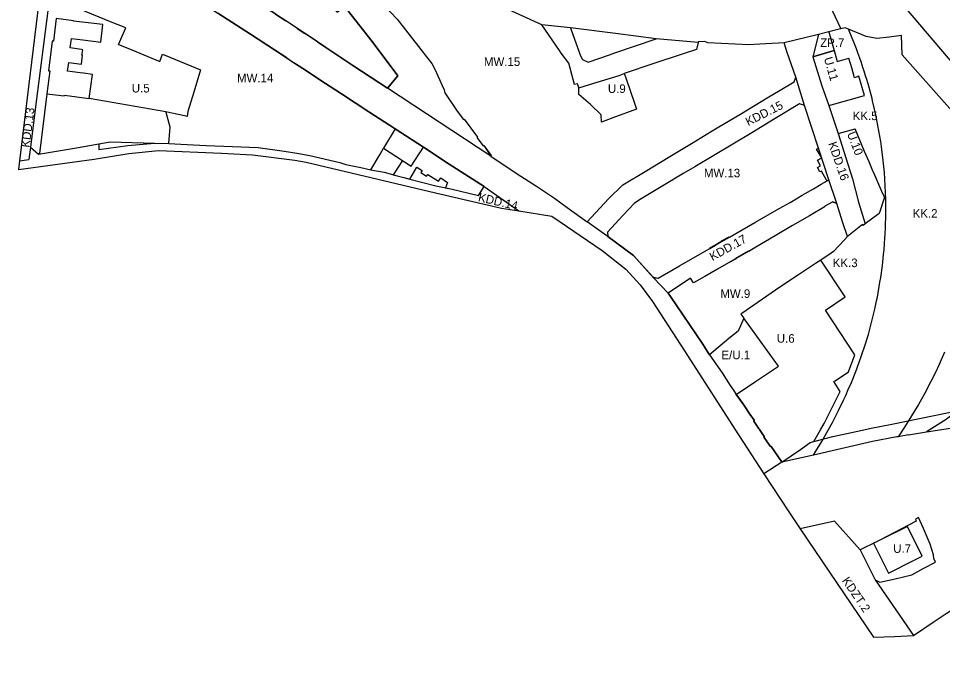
# Model space of a CAD drawing. Extents: x 7424719 to 7426158, y 5545504 to 5546892.
# Drawn here: x 7425136 to 7425675, y 5545534 to 5545910 of the extents above; entities that cross this region are included whole.
import ezdxf

# ---------------------------------------------------------------- set-up
doc = ezdxf.new("R2010")
doc.units = 0
for name, color, linetype in [('Linia Zabudowy Nieprzekraczalna', 7, 'Continuous'), ('Linia Zabudowy Obowiązujaca', 7, 'Continuous'), ('Linie Rozgraniczajace', 7, 'Continuous'), ('Oznaczenia Przeznaczenia', 7, 'Continuous')]:
    doc.layers.add(name, color=color, linetype=linetype)

msp = doc.modelspace()

# ---------------------------------------------------------------- linework, layer by layer
at = {"layer": 'Linia Zabudowy Nieprzekraczalna'}
for p, q in [((7425221.95, 5545855.04), (7425177.27, 5545862.88)), ((7425619.91, 5545782.28), (7425617.12, 5545790.15)), ((7425536.53, 5545758.98), (7425529.93, 5545755.27))]:
    msp.add_line(p, q, dxfattribs=at)
for points in [[(7425342.48, 5545896.07), (7425330.08, 5545911.69), (7425326.2, 5545916.65), (7425322, 5545913.22), (7425306.22, 5545929.93), (7425307.99, 5545931.44), (7425306.98, 5545931.69), (7425284.21, 5545937.96), (7425280.74, 5545938.92)], [(7425462.94, 5545868.99), (7425462.27, 5545871.4), (7425460.44, 5545870.89), (7425458.92, 5545876.89), (7425457.98, 5545880.44), (7425457.18, 5545883.45), (7425452.71, 5545889.29), (7425451.73, 5545890.74), (7425441.52, 5545905.84)], [(7425538.37, 5545895.3), (7425536.66, 5545895.99), (7425532.74, 5545895.93), (7425532.61, 5545895.42), (7425531.65, 5545891.5)], [(7425374.15, 5545887.09), (7425377.13, 5545883.26), (7425379.08, 5545879.51), (7425383.23, 5545870.4), (7425384.4, 5545867.84), (7425384.71, 5545866.06), (7425392.04, 5545855.48)], [(7425152.54, 5545865.55), (7425148.22, 5545830.64), (7425147.61, 5545830.39), (7425168.55, 5545833.86), (7425182.86, 5545836.3), (7425189.52, 5545837.43), (7425215.38, 5545836.72), (7425223.7, 5545836.49)], [(7425608.96, 5545858.71), (7425614.36, 5545842.32), (7425618.86, 5545828.14)], [(7425341.6, 5545821.17), (7425347.02, 5545830.29), (7425349.08, 5545833.88)], [(7425360.13, 5545826.6), (7425354.69, 5545818.22), (7425356.89, 5545817.58), (7425360.84, 5545816.68)], [(7425622.81, 5545815.98), (7425626.27, 5545802.36), (7425630.2, 5545789.7)], [(7425511.14, 5545811.23), (7425499.48, 5545804.26), (7425495.46, 5545801.77)], [(7425539.25, 5545713.16), (7425546.66, 5545702.61), (7425551.43, 5545695.31), (7425553.25, 5545692.5), (7425554.93, 5545690)], [(7425592.45, 5545657.95), (7425598.08, 5545661.94), (7425600.26, 5545662.54), (7425611.3, 5545665.5), (7425627.63, 5545668.96), (7425628.68, 5545669.19), (7425632.77, 5545670.07), (7425645.71, 5545672.72), (7425810.15, 5545706.28)]]:
    msp.add_lwpolyline(points, dxfattribs=at)
for points in [[(7425481.01, 5545888.36), (7425483.99, 5545889.38), (7425508.14, 5545897.68), (7425484.45, 5545900.73), (7425458.11, 5545904.1), (7425458.54, 5545902.88), (7425463.92, 5545887.7), (7425465.26, 5545885.66), (7425468.42, 5545884.03)], [(7425643.87, 5545585.67), (7425658.76, 5545593.24), (7425663.48, 5545595.64), (7425654.83, 5545612.88), (7425639.21, 5545605.19), (7425637.08, 5545604.14), (7425635.08, 5545603.18)]]:
    msp.add_lwpolyline(points, close=True, dxfattribs=at)
at = {"layer": 'Linia Zabudowy Obowiązujaca'}
msp.add_line((7425618.86, 5545828.14), (7425622.81, 5545815.98), dxfattribs=at)
for points in [[(7425280.74, 5545938.92), (7425271.38, 5545940.8), (7425262.7, 5545927.12), (7425267.77, 5545923.82), (7425267.93, 5545924.09), (7425272.74, 5545920.96), (7425272.54, 5545920.73), (7425280.99, 5545915.23), (7425281.18, 5545915.48), (7425286.07, 5545912.28), (7425285.91, 5545912.04), (7425291.9, 5545908.14), (7425292.06, 5545908.38), (7425298.88, 5545903.93), (7425298.67, 5545903.67), (7425303.12, 5545900.73), (7425303.34, 5545900.95), (7425310.54, 5545895.99), (7425310.47, 5545895.88), (7425315.42, 5545892.62), (7425331.12, 5545882.16), (7425351.27, 5545868.89), (7425357.35, 5545876.12), (7425342.48, 5545896.07)], [(7425441.52, 5545905.84), (7425406, 5545922.06), (7425398.41, 5545925.48), (7425384.75, 5545932.02), (7425380.53, 5545933.18), (7425380.79, 5545934.47), (7425361.98, 5545938.37), (7425355.08, 5545935.83), (7425344.31, 5545931.84), (7425340.9, 5545926.19)], [(7425340.9, 5545926.19), (7425357.03, 5545909.09), (7425370.81, 5545891.45), (7425374.15, 5545887.09)], [(7425360.84, 5545816.68), (7425364.36, 5545815.65), (7425368.49, 5545822.7), (7425371.48, 5545820.75), (7425370.72, 5545819.64), (7425374.18, 5545817.39), (7425374.9, 5545818.53), (7425381.16, 5545814.6), (7425382.41, 5545816.57), (7425385.82, 5545814.25), (7425386.36, 5545813.74), (7425385.19, 5545810.66), (7425388.32, 5545809.98), (7425404.43, 5545806.22), (7425407.69, 5545811.38), (7425387.39, 5545824.41), (7425372.32, 5545834.37), (7425355.76, 5545845.1), (7425340.37, 5545855.11), (7425324.58, 5545865.5), (7425311.75, 5545873.76), (7425304.02, 5545878.88), (7425299.79, 5545881.68), (7425296.67, 5545883.6), (7425296.6, 5545883.46), (7425292.48, 5545886.29), (7425292.6, 5545886.47), (7425285.44, 5545891.24), (7425271.34, 5545900.36), (7425252.35, 5545912.68)], [(7425392.04, 5545855.48), (7425395.72, 5545850.48), (7425396.14, 5545850.76), (7425403.95, 5545840.28), (7425403.55, 5545839.98), (7425407.27, 5545835.08), (7425407.66, 5545835.36), (7425411.91, 5545829.53), (7425411.67, 5545829.21), (7425427.04, 5545818.91), (7425438.24, 5545811.68), (7425448.82, 5545804.62), (7425456.25, 5545799.25), (7425467.98, 5545790.86), (7425480.31, 5545804.19), (7425488.77, 5545812.5), (7425501.66, 5545820.28), (7425516.17, 5545828.96), (7425529.68, 5545837.09), (7425539.86, 5545843.25), (7425543.71, 5545845.6), (7425558.03, 5545854.05), (7425573.05, 5545863.18), (7425580.63, 5545867.69), (7425588.71, 5545872.49), (7425589.64, 5545875.21), (7425584.72, 5545889.72), (7425582.81, 5545895.28), (7425568.74, 5545894.54), (7425562.22, 5545894.09), (7425538.37, 5545895.3)], [(7425531.65, 5545891.5), (7425522.67, 5545888.42), (7425506.88, 5545883.22), (7425489.51, 5545877.32)], [(7425612.14, 5545890.74), (7425599.6, 5545887.04), (7425604.91, 5545870.29), (7425608.96, 5545858.71)], [(7425495.46, 5545801.77), (7425488.97, 5545794.78), (7425479.68, 5545784.76), (7425479.93, 5545782.16), (7425494.97, 5545771.18), (7425506.2, 5545758.74), (7425506.35, 5545758.83), (7425506.66, 5545758.47), (7425509.31, 5545757.86), (7425521.77, 5545765.13), (7425528.25, 5545768.84), (7425539.46, 5545775.24), (7425539.34, 5545775.44), (7425539.88, 5545775.75), (7425542.1, 5545777.02), (7425542.46, 5545777.27), (7425545.97, 5545779.36), (7425546.38, 5545779.62), (7425550.73, 5545782.14), (7425550.84, 5545781.95), (7425550.95, 5545781.76), (7425565.77, 5545790.32), (7425579.89, 5545798.52), (7425586.31, 5545802.11), (7425590.85, 5545804.78), (7425593.43, 5545806.35), (7425599.92, 5545810.04), (7425604.45, 5545812.72), (7425607.93, 5545814.73), (7425607.49, 5545815.49), (7425604.61, 5545820.45), (7425603.74, 5545819.92), (7425602.31, 5545822.52), (7425604.17, 5545823.58), (7425602.38, 5545826.74), (7425604.79, 5545828.08), (7425601.83, 5545833.24), (7425602.95, 5545833.77), (7425594.8, 5545858.62), (7425591.92, 5545859.71), (7425577.67, 5545851.09), (7425563.96, 5545842.82), (7425530.71, 5545822.94), (7425524.41, 5545819.19), (7425511.14, 5545811.23)], [(7425223.7, 5545836.49), (7425230.61, 5545836.11), (7425245.49, 5545835.43), (7425260.79, 5545834.74), (7425275.88, 5545834.26), (7425291, 5545832.06), (7425298.36, 5545830.97), (7425305.98, 5545829.48), (7425323.44, 5545825.4), (7425327.04, 5545824.2), (7425335.7, 5545822.57), (7425341.6, 5545821.17)], [(7425349.08, 5545833.88), (7425360.13, 5545826.6)], [(7425617.12, 5545790.15), (7425613.63, 5545801.56), (7425611.22, 5545802.47), (7425606.64, 5545799.92), (7425606.73, 5545799.78), (7425597.65, 5545794.33), (7425587.78, 5545788.58), (7425577.55, 5545782.59), (7425566.29, 5545776.02), (7425562.19, 5545773.45), (7425562.1, 5545773.61), (7425554.75, 5545769.39), (7425554.77, 5545769.2), (7425550.37, 5545766.87), (7425544.05, 5545763.21), (7425536.53, 5545758.98)], [(7425529.93, 5545755.27), (7425528.14, 5545757.98), (7425515.23, 5545749.15), (7425516.56, 5545747.2), (7425534.99, 5545720.07), (7425539.25, 5545713.16)], [(7425555.2, 5545689.62), (7425559.1, 5545684.08), (7425562.89, 5545678.6), (7425565.41, 5545675.01), (7425565.18, 5545674.43), (7425571.21, 5545665.45), (7425571.22, 5545665), (7425574.75, 5545659.81), (7425575.35, 5545659.7), (7425581.25, 5545650.86), (7425581.5, 5545650.49), (7425592.45, 5545657.95)]]:
    msp.add_lwpolyline(points, dxfattribs=at)
msp.add_lwpolyline([(7425179.04, 5545876.88), (7425173.9, 5545877.53), (7425171.95, 5545877.77), (7425164.58, 5545878.73), (7425165.25, 5545883.79), (7425172.64, 5545882.83), (7425172.91, 5545884.65), (7425173.28, 5545888.02), (7425172.99, 5545888.05), (7425173.4, 5545891.27), (7425172.75, 5545891.35), (7425166.12, 5545892.29), (7425166.81, 5545897.8), (7425173.45, 5545896.96), (7425183.92, 5545895.77), (7425185.08, 5545906.02), (7425168.07, 5545907.92), (7425168.1, 5545908.19), (7425157.99, 5545909.45), (7425156.34, 5545896.18), (7425155.61, 5545896.27), (7425153.46, 5545878.96), (7425154.19, 5545878.87), (7425152.54, 5545865.55), (7425162.68, 5545864.27), (7425162.77, 5545864.68), (7425177.27, 5545862.88)], close=True, dxfattribs=at)
at = {"layer": 'Linie Rozgraniczajace'}
for p, q in [((7425978.47, 5545533.55), (7425205.67, 5546443.4)), ((7425609.01, 5545901.71), (7425612.14, 5545890.74)), ((7425411.67, 5545829.21), (7425351.27, 5545868.89)), ((7425222.08, 5545854.57), (7425221.95, 5545855.04)), ((7425224.45, 5545846), (7425222.08, 5545854.57)), ((7425223.7, 5545836.49), (7425224.45, 5545846)), ((7425614.36, 5545842.32), (7425624.4, 5545845.18)), ((7425611.22, 5545802.47), (7425613.63, 5545801.56)), ((7425515.23, 5545749.15), (7425506.63, 5545758.14)), ((7425581.5, 5545650.49), (7425571.06, 5545643.7)), ((7425664.15, 5545611.8), (7425661.37, 5545618.17)), ((7425657.45, 5545584.76), (7425664.36, 5545588.57)), ((7425647.58, 5545582.47), (7425657.45, 5545584.76)), ((7425636.06, 5545581.74), (7425658.39, 5545549.4))]:
    msp.add_line(p, q, dxfattribs=at)
for points in [[(7425151.54, 5545949.85), (7425136.55, 5545826.39), (7425135.93, 5545821.28), (7425180.05, 5545827.35), (7425200.35, 5545830.6), (7425217.76, 5545832.37), (7425254.45, 5545830.9), (7425272.5, 5545829.97), (7425297.34, 5545826.88), (7425303.93, 5545825.65), (7425379.35, 5545807.74), (7425417.93, 5545798.79), (7425427.91, 5545797.21), (7425447.26, 5545794.15), (7425476.64, 5545774.16), (7425490.4, 5545763.21), (7425498.87, 5545754.09), (7425505.93, 5545744.24), (7425524.66, 5545715.41), (7425554.05, 5545669.83), (7425571.06, 5545643.7), (7425585.53, 5545621.47), (7425592.25, 5545611.54), (7425635.03, 5545548.39)], [(7425151.54, 5545949.85), (7425151.94, 5545949.88), (7425160.68, 5545949.78), (7425156.01, 5545937.51), (7425154.82, 5545928.06), (7425153.94, 5545921.7), (7425153.22, 5545915.57), (7425146.14, 5545859.53), (7425142.98, 5545834.37), (7425142.02, 5545827.23)], [(7425213.97, 5545937.88), (7425235.03, 5545924), (7425252.35, 5545912.68), (7425271.34, 5545900.36), (7425285.44, 5545891.24), (7425299.79, 5545881.68), (7425304.02, 5545878.88), (7425311.75, 5545873.76), (7425324.58, 5545865.5), (7425340.37, 5545855.11), (7425355.76, 5545845.1), (7425372.32, 5545834.37), (7425387.39, 5545824.41), (7425407.69, 5545811.38)], [(7425307.99, 5545931.44), (7425306.22, 5545929.93), (7425322, 5545913.22), (7425326.2, 5545916.65), (7425330.08, 5545911.69), (7425342.48, 5545896.07), (7425357.35, 5545876.12), (7425351.27, 5545868.89), (7425331.12, 5545882.16), (7425315.42, 5545892.62), (7425310.47, 5545895.88), (7425291.9, 5545908.14), (7425262.7, 5545927.12)], [(7425340.9, 5545926.19), (7425357.03, 5545909.09), (7425370.81, 5545891.45), (7425374.15, 5545887.09), (7425377.13, 5545883.26), (7425379.08, 5545879.51), (7425383.23, 5545870.4), (7425384.4, 5545867.84), (7425384.71, 5545866.06), (7425392.04, 5545855.48), (7425395.72, 5545850.48), (7425396.14, 5545850.76), (7425403.95, 5545840.28), (7425403.55, 5545839.98), (7425407.27, 5545835.08), (7425407.66, 5545835.36), (7425411.67, 5545829.21)], [(7425194.35, 5545894.32), (7425198.5, 5545903.98), (7425189.71, 5545907.56), (7425172.04, 5545914.73), (7425169.28, 5545915.89), (7425164.22, 5545917.84), (7425153.94, 5545921.7)], [(7425609.38, 5545917.44), (7425616.05, 5545903.52), (7425615.83, 5545903.48), (7425609.01, 5545901.71), (7425602.96, 5545900.23), (7425582.81, 5545895.28), (7425568.74, 5545894.54), (7425562.22, 5545894.09), (7425538.37, 5545895.3), (7425536.66, 5545895.99), (7425532.74, 5545895.93), (7425532.61, 5545895.42), (7425508.14, 5545897.68), (7425484.45, 5545900.73), (7425458.11, 5545904.1), (7425441.52, 5545905.84), (7425406, 5545922.06)], [(7425599.93, 5545654.67), (7425601.39, 5545656.86), (7425604.86, 5545662.54), (7425607.88, 5545667.92), (7425611.15, 5545673.75), (7425613.48, 5545678.31), (7425614.69, 5545680.65), (7425617.59, 5545686.69), (7425618.92, 5545689.45), (7425620.33, 5545692.84), (7425622.19, 5545697.01), (7425624.71, 5545703.35), (7425626.54, 5545708.28), (7425628.25, 5545713.29), (7425629.8, 5545717.82), (7425632.02, 5545725.01), (7425633.85, 5545731.95), (7425635.8, 5545739.89), (7425636.84, 5545744.65), (7425637.33, 5545746.89), (7425638.79, 5545755.49), (7425639.26, 5545758.24), (7425640.21, 5545765.26), (7425640.9, 5545771.82), (7425641.19, 5545774.53), (7425641.7, 5545781.4), (7425641.84, 5545783.17), (7425642.05, 5545787.82), (7425642.21, 5545794.88), (7425642.25, 5545796.71), (7425642.24, 5545802.65), (7425642.2, 5545803.62), (7425642.05, 5545808.01), (7425641.92, 5545811.83), (7425641.65, 5545815.75), (7425641.37, 5545819.68), (7425640.69, 5545826.55), (7425639.92, 5545833.12), (7425639.26, 5545837.65), (7425638.17, 5545843.96), (7425636.39, 5545853.36), (7425635.67, 5545856.49), (7425634.53, 5545861.43), (7425634.19, 5545862.88), (7425633.03, 5545867.14), (7425632.24, 5545870.04), (7425631.07, 5545873.86), (7425630.42, 5545875.99), (7425629.55, 5545878.84), (7425629.07, 5545880.41), (7425627.77, 5545884.11), (7425627, 5545886.26), (7425625.87, 5545889.46), (7425625.01, 5545891.89), (7425623.85, 5545894.81), (7425622.57, 5545898.03), (7425620.49, 5545903.25)], [(7425620.49, 5545903.25), (7425618.56, 5545904.08), (7425616.05, 5545903.52)], [(7425636.98, 5545897.89), (7425630.66, 5545898.9), (7425620.49, 5545903.25)], [(7425602.96, 5545900.23), (7425599.6, 5545887.04)], [(7425651.34, 5545899.61), (7425644.25, 5545898.69), (7425636.98, 5545897.89)], [(7425696.1, 5545838.33), (7425651.74, 5545888.31), (7425651.34, 5545899.61)], [(7425194.35, 5545894.32), (7425199.69, 5545892.12), (7425218.4, 5545884.37), (7425220.09, 5545888.6), (7425224.2, 5545886.97), (7425242.18, 5545879.57), (7425238.37, 5545866.52), (7425234.87, 5545855.19), (7425234.37, 5545852.37), (7425233.8, 5545852.49), (7425225.51, 5545854.28), (7425221.95, 5545855.04)], [(7425599.6, 5545887.04), (7425604.91, 5545870.29), (7425608.96, 5545858.71), (7425614.36, 5545842.32), (7425618.86, 5545828.14), (7425622.81, 5545815.98), (7425626.27, 5545802.36), (7425630.2, 5545789.7), (7425628.93, 5545788.67), (7425628.52, 5545789.2), (7425619.91, 5545782.28), (7425617.12, 5545790.15), (7425613.63, 5545801.56), (7425608.93, 5545815.31), (7425602.95, 5545833.77), (7425594.8, 5545858.62), (7425589.64, 5545875.21), (7425584.72, 5545889.72), (7425582.81, 5545895.28)], [(7425599.6, 5545887.04), (7425612.14, 5545890.74), (7425613.82, 5545884.39), (7425620.6, 5545886.28)], [(7425608.96, 5545858.71), (7425620.74, 5545862.02), (7425629.74, 5545864.6), (7425626.52, 5545875.76), (7425623.99, 5545874.96), (7425622.3, 5545880.63), (7425620.6, 5545886.28)], [(7425489.51, 5545877.32), (7425490.19, 5545875.38), (7425493.32, 5545866.39), (7425495.13, 5545861.17), (7425496.7, 5545856.65), (7425482.84, 5545851.55), (7425476.25, 5545849.03), (7425476.13, 5545853.34), (7425469.78, 5545859.35), (7425462.94, 5545865.21), (7425462.94, 5545868.99), (7425469.17, 5545870.91), (7425486.61, 5545876.27), (7425489.51, 5545877.32)], [(7425594.8, 5545858.62), (7425591.92, 5545859.71), (7425577.67, 5545851.09), (7425563.96, 5545842.82), (7425530.71, 5545822.94), (7425524.41, 5545819.19), (7425511.14, 5545811.23), (7425499.48, 5545804.26), (7425495.46, 5545801.77), (7425488.97, 5545794.78), (7425479.68, 5545784.76), (7425479.93, 5545782.16), (7425476.09, 5545784.93), (7425467.98, 5545790.86), (7425480.31, 5545804.19), (7425488.77, 5545812.5), (7425501.66, 5545820.28), (7425516.17, 5545828.96), (7425529.68, 5545837.09), (7425539.86, 5545843.25), (7425543.71, 5545845.6), (7425558.03, 5545854.05), (7425573.05, 5545863.18), (7425580.63, 5545867.69), (7425588.71, 5545872.49), (7425589.64, 5545875.21)], [(7425355.76, 5545845.1), (7425349.08, 5545833.88), (7425365.16, 5545823.34), (7425372.32, 5545834.37)], [(7425642.2, 5545803.62), (7425641.39, 5545805.29), (7425639.98, 5545808.43), (7425635.79, 5545818.13), (7425634.5, 5545821.01), (7425632.47, 5545825.86), (7425629.74, 5545831.78), (7425624.4, 5545845.18)], [(7425142.98, 5545834.37), (7425147.61, 5545830.39), (7425168.55, 5545833.86), (7425176.41, 5545835.21), (7425182.86, 5545836.3), (7425182.91, 5545833.01)], [(7425182.91, 5545833.01), (7425199.71, 5545835.39), (7425215.38, 5545836.72), (7425223.7, 5545836.49), (7425230.61, 5545836.11), (7425245.49, 5545835.43), (7425260.79, 5545834.74), (7425275.88, 5545834.26), (7425291, 5545832.06), (7425298.36, 5545830.97), (7425305.98, 5545829.48), (7425323.44, 5545825.4), (7425327.04, 5545824.2), (7425335.7, 5545822.57), (7425341.6, 5545821.17), (7425349.34, 5545819.78), (7425356.89, 5545817.58), (7425360.84, 5545816.68), (7425364.36, 5545815.65), (7425379.46, 5545811.91), (7425388.32, 5545809.98), (7425404.43, 5545806.22), (7425407.69, 5545811.38), (7425427.91, 5545797.21)], [(7425136.55, 5545826.39), (7425142.02, 5545827.23)], [(7425411.67, 5545829.21), (7425427.04, 5545818.91), (7425438.24, 5545811.68), (7425448.82, 5545804.62), (7425456.25, 5545799.25), (7425467.98, 5545790.86)], [(7425506.63, 5545758.14), (7425509.31, 5545757.86), (7425521.77, 5545765.13), (7425528.25, 5545768.84), (7425539.46, 5545775.24), (7425542.77, 5545777.16), (7425550.95, 5545781.76), (7425565.77, 5545790.32), (7425579.89, 5545798.52), (7425586.31, 5545802.11), (7425590.85, 5545804.78), (7425593.43, 5545806.35), (7425599.92, 5545810.04), (7425604.45, 5545812.72), (7425608.93, 5545815.31)], [(7425641.39, 5545805.29), (7425638.37, 5545795.64), (7425630.2, 5545789.7)], [(7425611.22, 5545802.47), (7425606.64, 5545799.92), (7425606.73, 5545799.78), (7425597.65, 5545794.33), (7425587.78, 5545788.58), (7425577.55, 5545782.59), (7425566.29, 5545776.02), (7425550.37, 5545766.87), (7425544.05, 5545763.21), (7425536.53, 5545758.98)], [(7425506.63, 5545758.14), (7425494.97, 5545771.18), (7425479.93, 5545782.16)], [(7425619.91, 5545782.28), (7425617.91, 5545780.19), (7425611.6, 5545773.42), (7425610.37, 5545772.6), (7425604.19, 5545768.45)], [(7425604.19, 5545768.45), (7425601.14, 5545766.4), (7425591.22, 5545759.91), (7425580.43, 5545752.6), (7425565.17, 5545742.23), (7425558.24, 5545737.32), (7425557.61, 5545736.87), (7425559.25, 5545734.5)], [(7425581.5, 5545650.49), (7425592.45, 5545657.95), (7425598.08, 5545661.94), (7425600.26, 5545662.54), (7425602.58, 5545666.62), (7425604.18, 5545669.43), (7425606.27, 5545673.1), (7425615.61, 5545691.7), (7425611.97, 5545697.55), (7425612.61, 5545698.03), (7425620.45, 5545703.22), (7425624.11, 5545713.14), (7425606.94, 5545739.24), (7425618.44, 5545747), (7425604.19, 5545768.45)], [(7425536.53, 5545758.98), (7425529.93, 5545755.27), (7425528.14, 5545757.98), (7425515.23, 5545749.15), (7425516.56, 5545747.2)], [(7425539.25, 5545713.16), (7425534.99, 5545720.07), (7425516.56, 5545747.2), (7425515.23, 5545749.15)], [(7425694.74, 5545748.1), (7425697.53, 5545744.32), (7425718.27, 5545713.46), (7425723.27, 5545706.27), (7425705.53, 5545694.49), (7425701.55, 5545691.85), (7425682.3, 5545679.07), (7425678.48, 5545676.23), (7425677.43, 5545675.46), (7425665.92, 5545668.13)], [(7425676.45, 5545714.71), (7425673.93, 5545708.84), (7425673.3, 5545707.48), (7425671.2, 5545702.91), (7425668.59, 5545697.69), (7425664.71, 5545690.43), (7425661.2, 5545684.16), (7425657.17, 5545677.49), (7425654.71, 5545673.41), (7425653.03, 5545670.87), (7425649.37, 5545665.34)], [(7425581.5, 5545650.49), (7425581.25, 5545650.86), (7425575.35, 5545659.7), (7425574.75, 5545659.81), (7425571.22, 5545665), (7425571.21, 5545665.45), (7425565.18, 5545674.43), (7425565.41, 5545675.01), (7425562.89, 5545678.6), (7425559.1, 5545684.08), (7425554.93, 5545690)], [(7425655.55, 5545666.5), (7425665.92, 5545668.13), (7425682.53, 5545670.74), (7425738.91, 5545679.59), (7425748.67, 5545681.12)], [(7425655.55, 5545666.5), (7425649.37, 5545665.34), (7425648.73, 5545665.22), (7425634.41, 5545662.5)], [(7425634.41, 5545662.5), (7425599.93, 5545654.67), (7425581.5, 5545650.49)], [(7425627.27, 5545599.26), (7425612.26, 5545616.12), (7425592.25, 5545611.54)], [(7425661.37, 5545618.17), (7425659.45, 5545617.29), (7425659.94, 5545615.99), (7425639.21, 5545605.19), (7425637.08, 5545604.14), (7425635.63, 5545603.43), (7425628.32, 5545599.82), (7425627.27, 5545599.26), (7425636.06, 5545581.74), (7425638.63, 5545580.4), (7425647.58, 5545582.47)], [(7425670.33, 5545594.24), (7425670.07, 5545596.46), (7425668.14, 5545602.69), (7425664.15, 5545611.8)], [(7425664.36, 5545588.57), (7425671.26, 5545592.13), (7425670.33, 5545594.24)], [(7425635.03, 5545548.39), (7425647.38, 5545548.68), (7425658.39, 5545549.4), (7425669.8, 5545557.01), (7425677.41, 5545562.08), (7425686.97, 5545568.45)]]:
    msp.add_lwpolyline(points, dxfattribs=at)
msp.add_lwpolyline([(7425539.25, 5545713.16), (7425546.66, 5545702.61), (7425551.43, 5545695.31), (7425553.25, 5545692.5), (7425554.93, 5545690), (7425566.08, 5545697.54), (7425566.73, 5545697.98), (7425579.51, 5545706.6), (7425559.25, 5545734.5), (7425555.96, 5545727.01), (7425550.6, 5545722.62)], close=True, dxfattribs=at)

# ---------------------------------------------------------------- texts
at = {"layer": 'Oznaczenia Przeznaczenia'}
for s, p in [('ZP.7', (7425603.89, 5545892.83)), ('MW.15', (7425407.63, 5545881.8)), ('MW.14', (7425263.51, 5545872.28)), ('U.5', (7425202.09, 5545866.33)), ('U.9', (7425479.99, 5545866.06)), ('KK.5', (7425622.92, 5545850.18)), ('MW.13', (7425536.04, 5545816.79)), ('KK.2', (7425657.91, 5545793.23)), ('KK.3', (7425611.26, 5545764.36)), ('MW.9', (7425545.63, 5545746.4)), ('U.6', (7425578.6, 5545720.24)), ('E/U.1', (7425546.28, 5545710.6)), ('U.7', (7425646.53, 5545597.59))]:
    msp.add_text(s, height=5, dxfattribs=at).set_placement(p)
for s, rotation, p in [('U.11', 285.8846, (7425606.05, 5545886.23)), ('KDD.15', 26.9146, (7425561.9, 5545846.65)), ('KDD.13', 82.5604, (7425142.33, 5545833.95)), ('U.10', 290.746, (7425619.5, 5545842.31)), ('KDD.16', 289.1974, (7425608.5, 5545836.51)), ('KDD.14', 346.787, (7425403.93, 5545802.94)), ('KDD.17', 29.1428, (7425541.04, 5545767.84)), ('KDZT.2', 304.3019, (7425616.41, 5545581.37))]:
    msp.add_text(s, height=5, rotation=rotation, dxfattribs=at).set_placement(p)

doc.saveas('drawing.dxf')
